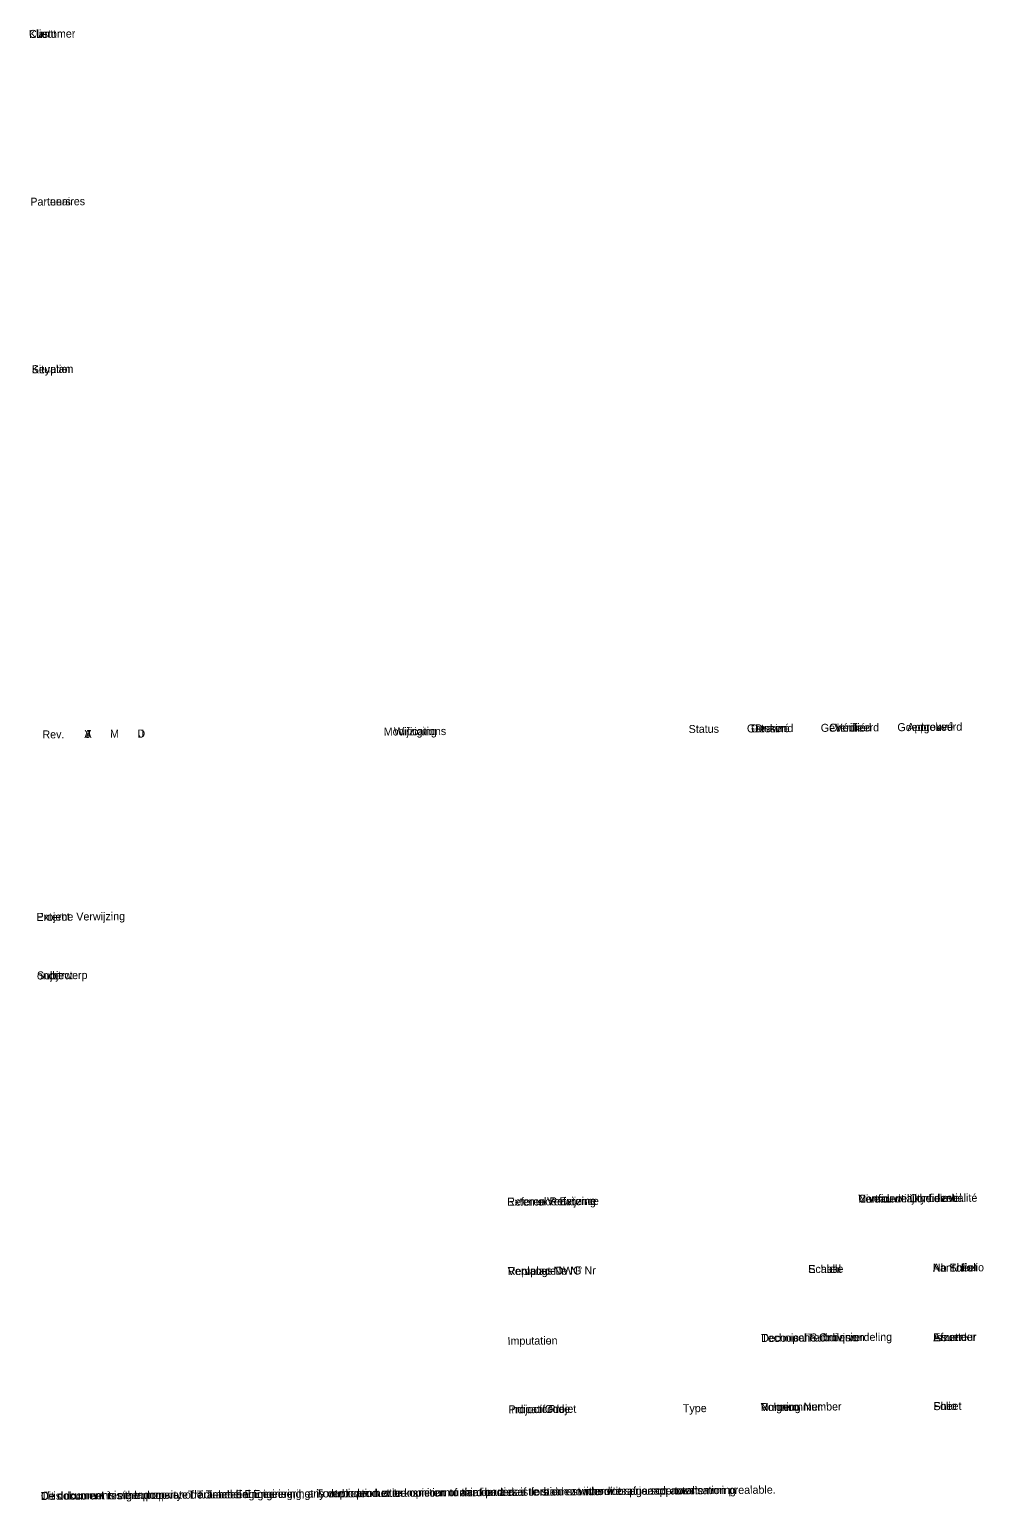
# Model space of a CAD drawing. Extents: x -932734 to -932083, y -737151 to -736752.
# Drawn here: x -932501.8 to -932412.5, y -737151.2 to -737013.3 of the extents above; entities that cross this region are included whole.
import ezdxf

# ---------------------------------------------------------------- set-up
doc = ezdxf.new("R2010")
doc.units = 0
for name, color, linetype in [('02 BORDER TEXT', 7, 'Continuous'), ('BorderColor', 7, 'Continuous'), ('WA_81_PODBARVENÍ SO', 7, 'Continuous')]:
    doc.layers.add(name, color=color, linetype=linetype)

msp = doc.modelspace()

# ---------------------------------------------------------------- texts
at = {"layer": '02 BORDER TEXT'}
for s, p in [('Client', (-932501.89, -737014.06)), ('Partenaires', (-932501.76, -737029.78)), ('Situation', (-932501.63, -737045.49)), ('Vérifié', (-932426.33, -737079.09)), ('Approuvé', (-932419.59, -737079.03)), ('Rev.', (-932500.63, -737079.72)), ('A', (-932496.7, -737079.68)), ('M', (-932494.29, -737079.66)), ('J', (-932491.61, -737079.64)), ('Modifications', (-932468.65, -737079.45)), ('Status', (-932440.08, -737079.21)), ('Dessiné', (-932434.24, -737079.16)), ('Projet', (-932501.19, -737096.82)), ('Sujet', (-932501.14, -737102.31)), ('Niveau de Confidentialité', (-932424.18, -737123.24)), ('Reference Externe', (-932457.08, -737123.52)), ('Remplace le N°', (-932457.03, -737130.02)), ('Echelle', (-932428.87, -737129.83)), ('Nb Folio', (-932417.2, -737129.71)), ('Imputation', (-932457.05, -737136.56)), ('Decoupe Technique', (-932433.28, -737136.29)), ('Emetteur', (-932417.16, -737136.22)), ('Indicatif Projet', (-932456.96, -737142.98)), ('Type', (-932440.62, -737142.88)), ('Numero', (-932433.33, -737142.77)), ('Folio', (-932417.14, -737142.68)), ('Ce document reste la propriete de Tractebel Engineering. Toute reproduction ou communication a des tiers en est interdite sans son autorisation prealable.', (-932500.77, -737151.09))]:
    msp.add_text(s, height=0.75, rotation=0.4883, dxfattribs=at).set_placement(p)
at = {"layer": 'BorderColor'}
for s, p in [('Customer', (-932501.89, -737014.06)), ('Partners', (-932501.76, -737029.78)), ('Keyplan', (-932501.63, -737045.49)), ('Approved', (-932419.59, -737079.03)), ('Rev.', (-932500.63, -737079.72)), ('Y', (-932496.7, -737079.68)), ('M', (-932494.29, -737079.66)), ('D', (-932491.73, -737079.64)), ('Modifications', (-932468.65, -737079.45)), ('Status', (-932440.08, -737079.21)), ('Drawn', (-932433.86, -737079.15)), ('Checked', (-932426.92, -737079.09)), ('Project', (-932501.19, -737096.82)), ('Subject', (-932501.14, -737102.31)), ('Confidentiality Level', (-932424.18, -737123.24)), ('External Reference', (-932457.08, -737123.52)), ('Replaces DWG Nr', (-932457.03, -737130.02)), ('Scale', (-932428.87, -737129.83)), ('Nb Sheet', (-932417.2, -737129.71)), ('Imputation', (-932457.05, -737136.56)), ('Technical Subdivision', (-932433.28, -737136.29)), ('Issuer', (-932417.16, -737136.22)), ('Project Code', (-932456.96, -737142.98)), ('Type', (-932440.62, -737142.88)), ('Running Number', (-932433.33, -737142.77)), ('Sheet', (-932417.14, -737142.68)), ('This document is the property of Tractebel Engineering, any duplication or transmition to third parties is forbidden without its prior approval.', (-932500.77, -737151.09))]:
    msp.add_text(s, height=0.75, rotation=0.4883, dxfattribs=at).set_placement(p)
at = {"layer": 'WA_81_PODBARVENÍ SO'}
for s, p in [('Klant', (-932501.89, -737014.06)), ('Partners', (-932501.76, -737029.78)), ('Situatie', (-932501.63, -737045.49)), ('Goedgekeurd', (-932420.52, -737079.04)), ('Rev.', (-932500.63, -737079.72)), ('J', (-932496.61, -737079.68)), ('M', (-932494.29, -737079.66)), ('D', (-932491.73, -737079.64)), ('Wijziging', (-932467.69, -737079.44)), ('Status', (-932440.08, -737079.21)), ('Getekend', (-932434.62, -737079.16)), ('Geverifieerd', (-932427.7, -737079.1)), ('Externe Verwijzing', (-932501.19, -737096.82)), ('onderwerp', (-932501.14, -737102.31)), ('Vertrouwelijkheidlevel', (-932424.18, -737123.24)), ('Externe Verwijzing', (-932457.08, -737123.52)), ('Vervangt Nr', (-932457.03, -737130.02)), ('Schaal', (-932428.87, -737129.83)), ('Aant. Folio', (-932417.2, -737129.71)), ('Imputatie', (-932457.05, -737136.56)), ('Technische Onderverdeling', (-932433.28, -737136.29)), ('Afzender', (-932417.16, -737136.22)), ('Projectcode', (-932456.96, -737142.98)), ('Type', (-932440.62, -737142.88)), ('Volgnummer', (-932433.33, -737142.77)), ('Folio', (-932417.14, -737142.68)), ('Dit dokument is eigendom van Tractebel Engineering; het is verboden het te kopieren of aan derden af te staan zonder voorafgaande toestemming', (-932500.77, -737151.09))]:
    msp.add_text(s, height=0.75, rotation=0.4883, dxfattribs=at).set_placement(p)

doc.saveas('drawing.dxf')
